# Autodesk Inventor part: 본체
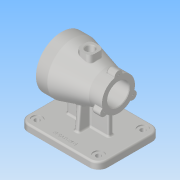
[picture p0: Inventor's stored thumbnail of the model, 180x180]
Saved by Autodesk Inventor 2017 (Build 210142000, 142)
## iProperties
Part Number: 본체
Material: 알루미늄 6061
Document SubType Name: Modeling
Designer: user
Density: 2.7 g/cm^3
Appearance: 알루미늄 - 평지
Mass: 1223.12 g
Surface Area: 899.626 cm^2
Volume: 453.008 cm^3
Author: user
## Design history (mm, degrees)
sketch "스케치3"
  geometry: L1 (70, 55)-(-70, 55); L2 (-70, 55)-(-70, -55); L3 (-70, -55)-(70, -55); L4 (70, -55)-(70, 55); L5 (70, 55)-(-70, -55); L6 (-70, 55)-(70, -55); 1 further point
  constraints: 12 end point, 2 midpoint, 2 parallel, 1 horizontal, 1 perpendicular
  dimensions: "d0" = 140 distance of L3.end L2.end; "d1" = 110 distance of L2.end L1.end
extrude "돌출1" new body sketch "스케치3" distance "d2" = 12; taper "d3" = 0 deg
sketch "스케치4"
  geometry: L1 (-50, 127)-(-30, 127); L2 (-30, 127)-(27, 111); L3 (27, 111)-(50, 111); L4 (50, 111)-(50, 82); L5 (50, 82)-(-50, 82); L6 (-50, 82)-(-50, 127); 2 further points
  constraints: 12 end point, 3 perpendicular, 1 horizontal, 1 midpoint, 1 parallel, 1 vertical alignment
  dimensions: "d4" = 82 distance from line of L5 point (0, 0); "d5" = 100 distance of L4.end L5.end; "d6" = 20 distance of L1.start L1.end; "d7" = 23 distance of L2.end L3.end; "d8" = 90 diameter of L1 L5; "d9" = 58 diameter of L3 L5; "d89" = 50 horizontal distance of point (0, 82) L1.start (derived)
revolve "회전1" sketch "스케치4" stored, may be unused: angle "d10" = 90 deg
sketch "스케치5"
  geometry: L1 (-37, -4)-(37, -4); L2 (37, -4)-(37, 4); L3 (37, 4)-(-37, 4); L4 (-37, 4)-(-37, -4); L5 (-37, -4)-(37, 4); L6 (37, -4)-(-37, 4); L7 (-4, -24)-(4, -24); L8 (4, -24)-(4, 24); L9 (4, 24)-(-4, 24); L10 (-4, 24)-(-4, -24); L11 (-4, -24)-(4, 24); L12 (4, -24)-(-4, 24); 1 further point
  constraints: 24 end point, 4 midpoint, 4 parallel, 2 horizontal, 2 perpendicular
  dimensions: "d11" = 74 distance of L3.end L2.end; "d12" = 8 distance of L2.end L1.end; "d13" = 8 distance of L9.end L8.end; "d14" = 48 distance of L8.end L7.end; "d90" = 24 distance from line of L7 point (0, 0) (derived); "d91" = 24 distance from line of L9 point (0, 0) (derived)
extrude "돌출2" join sketch "스케치5" stored distance "d15" = 12; taper "d16" = 0 deg
feature "면 기울기1" dims angle "d17" = 5 deg
feature "면 기울기2" dims angle "d18" = 5 deg
node "작업 평면1"
sketch "스케치6"
  geometry: L1 (12.5, 12.5)-(-12.5, 12.5); L2 (-12.5, 12.5)-(-12.5, -12.5); L3 (-12.5, -12.5)-(12.5, -12.5); L4 (12.5, -12.5)-(12.5, 12.5); L5 (12.5, 12.5)-(-12.5, -12.5); L6 (-12.5, 12.5)-(12.5, -12.5); 1 further point
  constraints: 12 end point, 2 midpoint, 2 parallel, 1 horizontal, 1 perpendicular
  dimensions: "d20" = 25 distance of L3.end L2.end; "d21" = 25 distance of L2.end L1.end
extrude "돌출3" join sketch "스케치6" stored distance "d22" = 10; taper "d23" = 0 deg
sketch "스케치7"
  geometry: L1 (0, 0)-(0, 29); L2 (0, 0)-(-25.115, -14.5); L3 (0, 0)-(25.115, -14.5); C1 r 7 at (0, 29); C2 r 7 at (-25.115, -14.5); C3 r 7 at (25.115, -14.5); A1 r 29 centre (0, 0) between (0, 29) and (-25.115, -14.5) reference; 2 further points
  constraints: 6 end point, 3 centre point, 3 coincident, 3 point on circle, 1 vertical
  dimensions: "d25" = 120 deg angle of L2 L1; "d26" = 120 deg angle of L3 L1; "d28" = 14 diameter of C1; "d29" = 14 diameter of C2; "d30" = 14 diameter of C3
extrude "돌출4" join sketch "스케치7" distance "d31" = 15; taper "d32" = 0 deg
sketch "스케치8"
  geometry: A1 r 7 centre (0, 0) between (6.949, -0.845) and (-6.949, -0.845) reference; A2 r 7 centre (-25.115, -43.5) between (-27.858, -37.06) and (-20.909, -49.095) reference; A3 r 7 centre (25.115, -43.5) between (20.909, -49.095) and (27.858, -37.06) reference; 4 further points
  constraints: 3 coincident
hole "구멍1" sketch "스케치8" at (0, 0), (25.115, -43.5), (-25.115, -43.5) diameter "d33" = 3.242; stored, may be unused: countersink angle "d37" = 90 deg, drill point angle "d39" = 118 deg; dims "d34" = 9, "d35" = 4, "d36" = 2, "d38" = 11
sketch "스케치9"
  geometry: L1 (-50, 37)-(-50, 127) reference; L2 (-50, 82)-(50, 82); L3 (-50, 82)-(-50, 113); L4 (-50, 113)-(-30, 113); L5 (-27, 110)-(-27, 110); L6 (-24, 107)-(17, 107); L7 (20, 104)-(20, 104); L8 (23, 101)-(50, 101); L9 (50, 101)-(50, 82); A1 r 3 centre (-30, 110) between (-27, 110) and (-30, 113); A2 r 3 centre (-24, 110) between (-27, 110) and (-24, 107); A3 r 3 centre (17, 104) between (20, 104) and (17, 107); A4 r 3 centre (23, 104) between (20, 104) and (23, 101); 5 further points
  constraints: 16 end point, 9 point on line, 8 point on circle, 8 tangent, 5 perpendicular, 4 centre point, 3 equal radius, 2 horizontal, 1 midpoint
  dimensions: "d40" = 100 distance of L2.start L2.end; "d41" = 23 distance of L3.end point (-27, 113); "d42" = 30 distance of point (20, 101) L8.end; "d43" = 47 distance of point (-27, 107) point (20, 107) (derived); "d44" = 62 diameter of L4 L2; "d45" = 50 diameter of L6 L2; "d46" = 38 diameter of L8 L2; "d47" = 3 radius of A1
revolve "회전2" sketch "스케치9" stored, may be unused: angle "d48" = 90 deg
sketch "스케치10"
  geometry: C1 r 7.5 at (0, 0); 1 further point
  constraints: 1 centre point, 1 coincident
  dimensions: "d49" = 15 diameter of C1
extrude "돌출5" cut sketch "스케치10" distance "d50" = 50; taper "d51" = 0 deg
sketch "스케치11"
  geometry: L1 (0, 0)-(0, 40); L2 (0, 0)-(-34.641, 20); L3 (0, 0)-(-34.641, -20); L4 (0, 0)-(0, -40); L5 (0, 0)-(34.641, -20); L6 (0, 0)-(34.641, 20); C1 r 45 at (0, 0) reference; A1 r 40 centre (0, 0) between (0, 40) and (-34.641, 20); 7 further points
  constraints: 12 end point, 7 coincident, 6 point on circle, 2 vertical, 1 centre point, 1 point on line
  dimensions: "d52" = 80 diameter of A1; "d53" = 60 deg angle of L2 L1; "d54" = 60 deg angle of L3 L2; "d55" = 60 deg angle of L5 L4
hole "구멍2" sketch "스케치11" at (0, 40), (-34.641, 20), (-34.641, -20), (0, -40), (34.641, -20), (34.641, 20) diameter "d56" = 3.242; stored, may be unused: countersink angle "d60" = 90 deg, drill point angle "d62" = 118 deg; dims "d57" = 9, "d58" = 4, "d59" = 2, "d61" = 11
fillet "모깎기1" dims "d63" = 16
sketch "스케치12"
  geometry: C1 r 9 at (-54, 39); C2 r 9 at (54, 39); C3 r 9 at (54, -39); C4 r 9 at (-54, -39); A1 r 16 centre (54, 39) between (70, 39) and (54, 55) reference; A2 r 16 centre (-54, 39) between (-54, 55) and (-70, 39) reference; A3 r 16 centre (-54, -39) between (-70, -39) and (-54, -55) reference; A4 r 16 centre (54, -39) between (54, -55) and (70, -39) reference; 1 further point
  constraints: 4 centre point, 4 coincident
  dimensions: "d64" = 18 diameter of C1; "d65" = 18 diameter of C2; "d66" = 18 diameter of C3; "d67" = 18 diameter of C4
extrude "돌출6" cut sketch "스케치12" distance "d68" = 2; taper "d69" = 0 deg
sketch "스케치13"
  geometry: C1 r 4.5 at (-54, 39); C2 r 4.5 at (54, 39); C3 r 4.5 at (54, -39); C4 r 4.5 at (-54, -39); A1 r 16 centre (54, 39) between (70, 39) and (54, 55) reference; A2 r 16 centre (-54, 39) between (-54, 55) and (-70, 39) reference; A3 r 16 centre (-54, -39) between (-70, -39) and (-54, -55) reference; A4 r 16 centre (54, -39) between (54, -55) and (70, -39) reference; 1 further point
  constraints: 4 centre point, 4 coincident
  dimensions: "d70" = 9 diameter of C1; "d71" = 9 diameter of C2; "d72" = 9 diameter of C3; "d73" = 9 diameter of C4
extrude "돌출7" cut sketch "스케치13" stored distance "d74" = 10; taper "d75" = 0 deg
chamfer "모따기1" distance "d76" = 1; stored, may be unused: second distance "d77" = 2, angle "d78" = 45 deg
fillet "모깎기2" dims "d79" = 8
fillet "모깎기3" dims "d80" = 1
fillet "모깎기4" dims "d81" = 3
fillet "모깎기5" dims "d82" = 3
fillet "모깎기6" dims "d83" = 3
fillet "모깎기7" dims "d84" = 1
node "작업 평면2"
sketch "스케치15"
  geometry: 2 further points
  constraints: 1 other
feature "엠보싱1" sketch "스케치15" dims "d0" = 140, "d1" = 110, "d11" = 74, "d12" = 8, "d86" = 0.5, "d87" = 0
fillet "모깎기8" dims "d88" = 3
node "솔리드1"
other parameters: "d19" = 127, "d85" = 13
